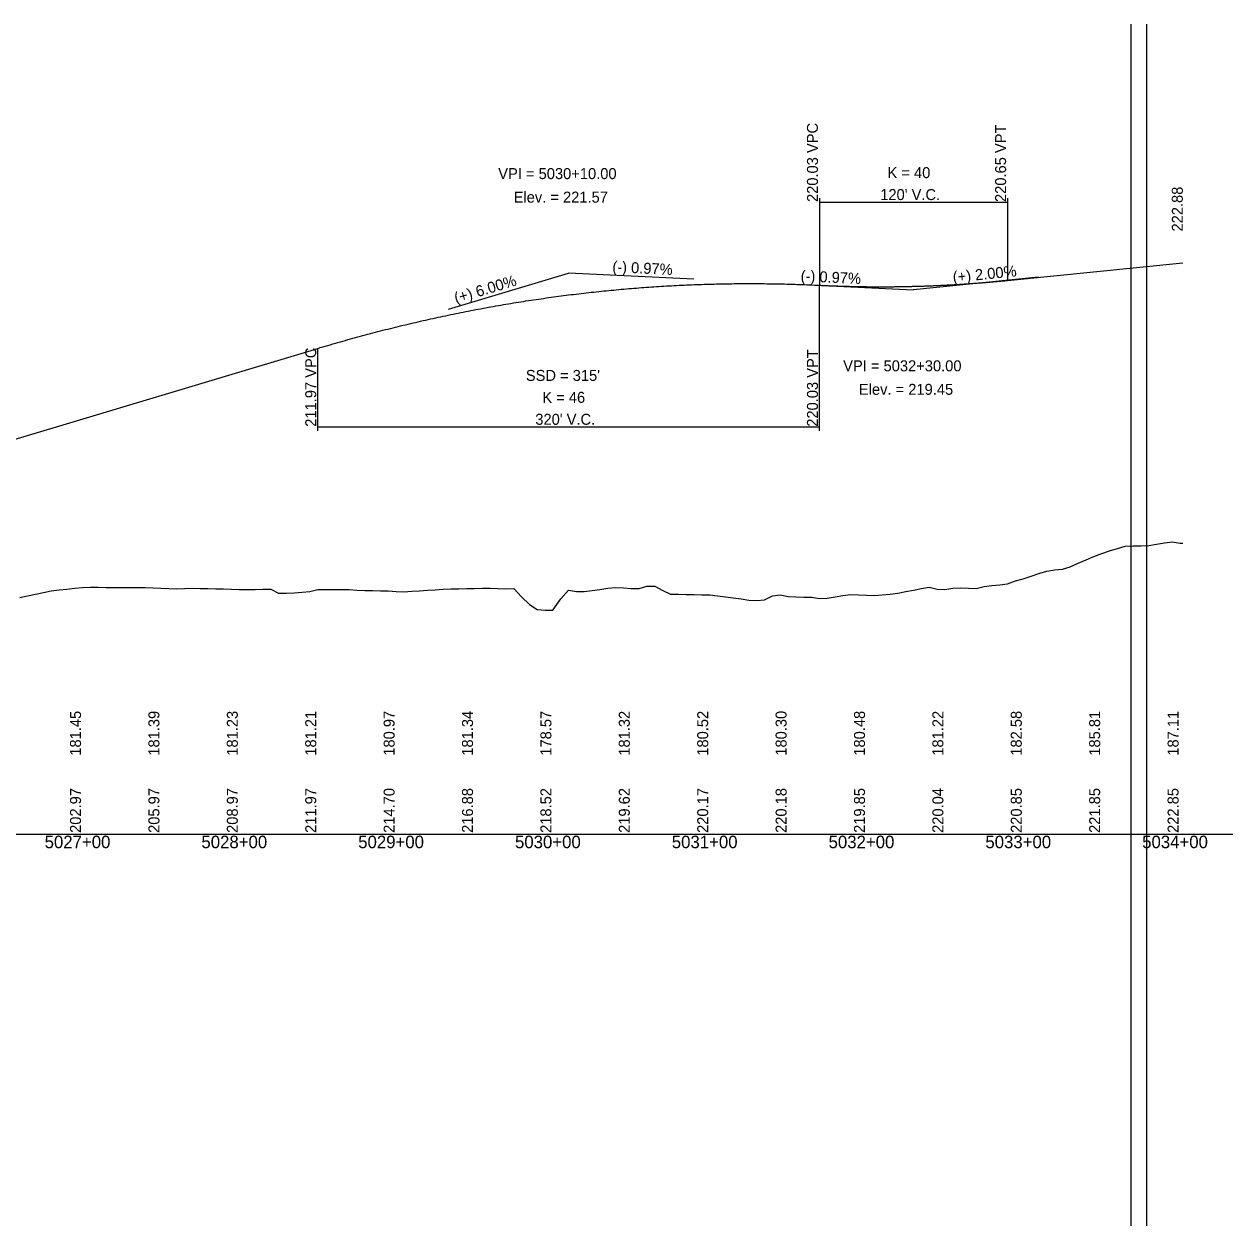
# Model space of a CAD drawing. Extents: x 1876258 to 1932803, y 754739 to 837911.
# Drawn here: x 1915332 to 1916098, y 787739 to 788506 of the extents above; entities that cross this region are included whole.
import ezdxf

# ---------------------------------------------------------------- set-up
doc = ezdxf.new("R2010")
doc.units = 0
for name, color, linetype in [('Default', 7, 'Continuous'), ('RD_DDB_GradeTX', 7, 'Continuous'), ('RD_DDB_Profile_EX', 7, 'Continuous'), ('RD_DDB_Profile_Lbl', 7, 'Continuous'), ('RD_DDB_Profile_PR', 7, 'Continuous'), ('RD_DDB_StaTX', 7, 'Continuous'), ('RD_DDB_StripGrade', 7, 'Continuous'), ('RD_DDB_VCLbl', 7, 'Continuous'), ('RD_GPK_Profile_Cell', 7, 'Continuous')]:
    doc.layers.add(name, color=color, linetype=linetype)

msp = doc.modelspace()

# ---------------------------------------------------------------- linework, layer by layer
at = {"layer": 'Default'}
for p, q in [((1916038.02, 787739.14), (1916038.02, 788505.91)), ((1916048.02, 787739.14), (1916048.02, 788505.91))]:
    msp.add_line(p, q, dxfattribs=at)
at = {"layer": 'RD_DDB_GradeTX'}
for p, q in [((1915602.66, 788324.01), (1915679.29, 788347)), ((1915759.2, 788343.14), (1915679.29, 788347)), ((1915819.38, 788340.23), (1915899.29, 788336.37)), ((1915978.89, 788344.33), (1915899.29, 788336.37))]:
    msp.add_line(p, q, dxfattribs=at)
at = {"layer": 'RD_DDB_Profile_EX'}
for points in [[(1915964.26, 788150.67), (1915969.26, 788152.05), (1915974.26, 788153.65), (1915979.26, 788155.28), (1915984.26, 788156.9), (1915989.26, 788157.82), (1915994.26, 788158.06), (1915999.26, 788159.6), (1916004.26, 788161.87), (1916009.26, 788164.15), (1916014.26, 788166.26), (1916019.26, 788168.19), (1916024.26, 788169.77), (1916029.26, 788171.31), (1916034.26, 788172.84), (1916039.26, 788172.97), (1916044.26, 788173.11), (1916049.26, 788173.25), (1916054.26, 788174.02), (1916059.26, 788175.01), (1916064.26, 788175.64), (1916069.26, 788174.7), (1916071.01, 788174.7)], [(1915964.26, 788150.67), (1915969.26, 788152.05), (1915974.26, 788153.65), (1915979.26, 788155.28), (1915984.26, 788156.9), (1915989.26, 788157.82), (1915994.26, 788158.06), (1915999.26, 788159.6), (1916004.26, 788161.87), (1916009.26, 788164.15), (1916014.26, 788166.26), (1916019.26, 788168.19), (1916024.26, 788169.77), (1916029.26, 788171.31), (1916034.26, 788172.84), (1916039.26, 788172.97), (1916044.26, 788173.11), (1916049.26, 788173.25), (1916054.26, 788174.02), (1916059.26, 788175.01), (1916064.26, 788175.64), (1916069.26, 788174.7), (1916071.01, 788174.7)], [(1915464.26, 788145.4), (1915469.26, 788145.27), (1915474.26, 788145.11), (1915479.26, 788145.23), (1915484.26, 788145.34), (1915489.26, 788145.46), (1915494.26, 788142.91), (1915499.26, 788142.81), (1915504.26, 788143.14), (1915509.26, 788143.48), (1915514.26, 788143.86), (1915519.26, 788145.22), (1915524.26, 788145.21), (1915529.26, 788145.22), (1915534.26, 788145.24), (1915539.26, 788145.16), (1915544.26, 788144.72), (1915549.26, 788144.6), (1915554.26, 788144.51), (1915559.26, 788144.42), (1915564.26, 788144.33), (1915569.26, 788143.98), (1915574.26, 788143.77), (1915579.26, 788144.09), (1915584.26, 788144.41), (1915589.26, 788144.74), (1915594.26, 788145.06), (1915599.26, 788145.38), (1915604.26, 788145.5), (1915609.26, 788145.62), (1915614.26, 788145.74), (1915619.26, 788145.85), (1915624.26, 788145.97), (1915629.26, 788146.07), (1915634.26, 788145.86), (1915639.26, 788145.65), (1915644.26, 788145.91), (1915649.26, 788140.45), (1915654.26, 788135.5), (1915659.26, 788132.36), (1915664.26, 788132.01), (1915669.26, 788131.93), (1915674.26, 788139.31), (1915679.26, 788144.73), (1915684.26, 788143.96), (1915689.26, 788143.87), (1915694.26, 788144.5), (1915699.26, 788145.27), (1915704.26, 788146.03), (1915709.26, 788146.52), (1915714.26, 788146.24), (1915719.26, 788145.75), (1915724.26, 788145.82), (1915729.26, 788147.31), (1915734.26, 788147.32), (1915739.26, 788144.61), (1915744.26, 788142.28), (1915749.26, 788142.15), (1915754.26, 788142.02), (1915759.26, 788141.88), (1915764.26, 788141.81), (1915769.26, 788141.77), (1915774.26, 788141.22), (1915779.26, 788140.52), (1915784.26, 788139.85), (1915789.26, 788139.17), (1915794.26, 788138.45), (1915799.26, 788138.08), (1915804.26, 788138.61), (1915809.26, 788141.18), (1915814.26, 788141.76), (1915819.26, 788140.63), (1915824.26, 788140.51), (1915829.26, 788140.39), (1915834.26, 788140.26), (1915839.26, 788139.41), (1915844.26, 788139.6), (1915849.26, 788140.43), (1915854.26, 788141.25), (1915859.26, 788142.03), (1915864.26, 788141.79), (1915869.26, 788141.55), (1915874.26, 788141.4), (1915879.26, 788141.73), (1915884.26, 788142.28), (1915889.26, 788142.89), (1915894.26, 788143.81), (1915899.26, 788144.75), (1915904.26, 788145.8), (1915909.26, 788146.69), (1915914.26, 788145.49), (1915919.26, 788145.24), (1915924.26, 788146.02), (1915929.26, 788146.24), (1915934.26, 788146.03), (1915939.26, 788145.71), (1915944.26, 788147.09), (1915949.26, 788147.66), (1915954.26, 788148.22), (1915959.26, 788148.88), (1915964.26, 788150.67)], [(1915464.26, 788145.4), (1915469.26, 788145.27), (1915474.26, 788145.11), (1915479.26, 788145.23), (1915484.26, 788145.34), (1915489.26, 788145.46), (1915494.26, 788142.91), (1915499.26, 788142.81), (1915504.26, 788143.14), (1915509.26, 788143.48), (1915514.26, 788143.86), (1915519.26, 788145.22), (1915524.26, 788145.21), (1915529.26, 788145.22), (1915534.26, 788145.24), (1915539.26, 788145.16), (1915544.26, 788144.72), (1915549.26, 788144.6), (1915554.26, 788144.51), (1915559.26, 788144.42), (1915564.26, 788144.33), (1915569.26, 788143.98), (1915574.26, 788143.77), (1915579.26, 788144.09), (1915584.26, 788144.41), (1915589.26, 788144.74), (1915594.26, 788145.06), (1915599.26, 788145.38), (1915604.26, 788145.5), (1915609.26, 788145.62), (1915614.26, 788145.74), (1915619.26, 788145.85), (1915624.26, 788145.97), (1915629.26, 788146.07), (1915634.26, 788145.86), (1915639.26, 788145.65), (1915644.26, 788145.91), (1915649.26, 788140.45), (1915654.26, 788135.5), (1915659.26, 788132.36), (1915664.26, 788132.01), (1915669.26, 788131.93), (1915674.26, 788139.31), (1915679.26, 788144.73), (1915684.26, 788143.96), (1915689.26, 788143.87), (1915694.26, 788144.5), (1915699.26, 788145.27), (1915704.26, 788146.03), (1915709.26, 788146.52), (1915714.26, 788146.24), (1915719.26, 788145.75), (1915724.26, 788145.82), (1915729.26, 788147.31), (1915734.26, 788147.32), (1915739.26, 788144.61), (1915744.26, 788142.28), (1915749.26, 788142.15), (1915754.26, 788142.02), (1915759.26, 788141.88), (1915764.26, 788141.81), (1915769.26, 788141.77), (1915774.26, 788141.22), (1915779.26, 788140.52), (1915784.26, 788139.85), (1915789.26, 788139.17), (1915794.26, 788138.45), (1915799.26, 788138.08), (1915804.26, 788138.61), (1915809.26, 788141.18), (1915814.26, 788141.76), (1915819.26, 788140.63), (1915824.26, 788140.51), (1915829.26, 788140.39), (1915834.26, 788140.26), (1915839.26, 788139.41), (1915844.26, 788139.6), (1915849.26, 788140.43), (1915854.26, 788141.25), (1915859.26, 788142.03), (1915864.26, 788141.79), (1915869.26, 788141.55), (1915874.26, 788141.4), (1915879.26, 788141.73), (1915884.26, 788142.28), (1915889.26, 788142.89), (1915894.26, 788143.81), (1915899.26, 788144.75), (1915904.26, 788145.8), (1915909.26, 788146.69), (1915914.26, 788145.49), (1915919.26, 788145.24), (1915924.26, 788146.02), (1915929.26, 788146.24), (1915934.26, 788146.03), (1915939.26, 788145.71), (1915944.26, 788147.09), (1915949.26, 788147.66), (1915954.26, 788148.22), (1915959.26, 788148.88), (1915964.26, 788150.67)], [(1915329.26, 788140.12), (1915334.26, 788141.16), (1915339.26, 788142.21), (1915344.26, 788143.25), (1915349.26, 788144.29), (1915354.26, 788144.97), (1915359.26, 788145.44), (1915364.26, 788145.92), (1915369.26, 788146.4), (1915374.26, 788146.61), (1915379.26, 788146.57), (1915384.26, 788146.54), (1915389.26, 788146.51), (1915394.26, 788146.48), (1915399.26, 788146.45), (1915404.26, 788146.42), (1915409.26, 788146.55), (1915414.26, 788146.32), (1915419.26, 788146.08), (1915424.26, 788145.85), (1915429.26, 788145.55), (1915434.26, 788145.85), (1915439.26, 788146.02), (1915444.26, 788145.89), (1915449.26, 788145.77), (1915454.26, 788145.65), (1915459.26, 788145.52), (1915464.26, 788145.4)], [(1915329.26, 788140.12), (1915334.26, 788141.16), (1915339.26, 788142.21), (1915344.26, 788143.25), (1915349.26, 788144.29), (1915354.26, 788144.97), (1915359.26, 788145.44), (1915364.26, 788145.92), (1915369.26, 788146.4), (1915374.26, 788146.61), (1915379.26, 788146.57), (1915384.26, 788146.54), (1915389.26, 788146.51), (1915394.26, 788146.48), (1915399.26, 788146.45), (1915404.26, 788146.42), (1915409.26, 788146.55), (1915414.26, 788146.32), (1915419.26, 788146.08), (1915424.26, 788145.85), (1915429.26, 788145.55), (1915434.26, 788145.85), (1915439.26, 788146.02), (1915444.26, 788145.89), (1915449.26, 788145.77), (1915454.26, 788145.65), (1915459.26, 788145.52), (1915464.26, 788145.4)]]:
    msp.add_lwpolyline(points, dxfattribs=at)
at = {"layer": 'RD_DDB_Profile_PR'}
for p, q in [((1915959.29, 788342.37), (1916071.01, 788353.54)), ((1915284.29, 788228.5), (1915519.29, 788299))]:
    msp.add_line(p, q, dxfattribs=at)
for points in [[(1915519.29, 788299), (1915525.69, 788300.9), (1915532.09, 788302.75), (1915538.49, 788304.56), (1915544.89, 788306.32), (1915551.29, 788308.04), (1915557.69, 788309.72), (1915564.09, 788311.35), (1915570.49, 788312.93), (1915576.89, 788314.47), (1915583.29, 788315.97), (1915589.69, 788317.42), (1915596.09, 788318.83), (1915602.49, 788320.19), (1915608.89, 788321.51), (1915615.29, 788322.78), (1915621.69, 788324.01), (1915628.09, 788325.2), (1915634.49, 788326.34), (1915640.89, 788327.43), (1915647.29, 788328.48), (1915653.69, 788329.49), (1915660.09, 788330.45), (1915666.49, 788331.37), (1915672.89, 788332.24), (1915679.29, 788333.07), (1915685.69, 788333.85), (1915692.09, 788334.59), (1915698.49, 788335.28), (1915704.89, 788335.93), (1915711.29, 788336.54), (1915717.69, 788337.1), (1915724.09, 788337.61), (1915730.49, 788338.08), (1915736.89, 788338.51), (1915743.29, 788338.89), (1915749.69, 788339.23), (1915756.09, 788339.52), (1915762.49, 788339.77), (1915768.89, 788339.97), (1915775.29, 788340.13), (1915781.69, 788340.25), (1915788.09, 788340.32), (1915794.49, 788340.34), (1915800.89, 788340.32), (1915807.29, 788340.26), (1915813.69, 788340.15), (1915820.09, 788340), (1915826.49, 788339.8), (1915832.89, 788339.56), (1915839.29, 788339.27)], [(1915839.29, 788339.27), (1915841.69, 788339.16), (1915844.09, 788339.05), (1915846.49, 788338.95), (1915848.89, 788338.86), (1915851.29, 788338.78), (1915853.69, 788338.7), (1915856.09, 788338.63), (1915858.49, 788338.57), (1915860.89, 788338.51), (1915863.29, 788338.47), (1915865.69, 788338.43), (1915868.09, 788338.39), (1915870.49, 788338.36), (1915872.89, 788338.34), (1915875.29, 788338.33), (1915877.69, 788338.33), (1915880.09, 788338.33), (1915882.49, 788338.34), (1915884.89, 788338.35), (1915887.29, 788338.37), (1915889.69, 788338.4), (1915892.09, 788338.44), (1915894.49, 788338.49), (1915896.89, 788338.54), (1915899.29, 788338.6), (1915901.69, 788338.66), (1915904.09, 788338.73), (1915906.49, 788338.81), (1915908.89, 788338.9), (1915911.29, 788339), (1915913.69, 788339.1), (1915916.09, 788339.2), (1915918.49, 788339.32), (1915920.89, 788339.44), (1915923.29, 788339.57), (1915925.69, 788339.71), (1915928.09, 788339.85), (1915930.49, 788340), (1915932.89, 788340.16), (1915935.29, 788340.33), (1915937.69, 788340.5), (1915940.09, 788340.68), (1915942.49, 788340.87), (1915944.89, 788341.06), (1915947.29, 788341.26), (1915949.69, 788341.47), (1915952.09, 788341.68), (1915954.49, 788341.91), (1915956.89, 788342.13), (1915959.29, 788342.37)]]:
    msp.add_spline(points, degree=3, dxfattribs=at)
at = {"layer": 'RD_DDB_VCLbl'}
for p, q in [((1915839.29, 788394.87), (1915839.29, 788339.27)), ((1915839.29, 788392.37), (1915959.29, 788392.37)), ((1915959.29, 788394.87), (1915959.29, 788342.37)), ((1915839.29, 788246.5), (1915839.29, 788339.27)), ((1915519.29, 788246.5), (1915519.29, 788299)), ((1915519.29, 788249), (1915839.29, 788249))]:
    msp.add_line(p, q, dxfattribs=at)
at = {"layer": 'RD_GPK_Profile_Cell'}
msp.add_line((1914544, 787989.14), (1916244, 787989.14), dxfattribs=at)

# ---------------------------------------------------------------- texts
at = {"layer": 'RD_DDB_GradeTX'}
for s, rotation, p in [('(-) 0.97%', 357.23394, (1915707.03, 788347.66)), ('(-) 0.97%', 357.23394, (1915827.15, 788341.86)), ('(+) 2.00%', 5.71056, (1915924.63, 788340.92)), ('(+) 6.00%', 16.69924, (1915607.52, 788327.56))]:
    msp.add_text(s, height=7, rotation=rotation, dxfattribs=at).set_placement(p)
at = {"layer": 'RD_DDB_Profile_Lbl'}
for s, p in [('VPI = 5030+10.00', (1915634.39, 788407)), ('Elev. = 221.57', (1915644.23, 788392)), ('VPI = 5032+30.00', (1915854.39, 788284.37)), ('Elev. = 219.45', (1915864.43, 788269.37))]:
    msp.add_text(s, height=7, dxfattribs=at).set_placement(p)
msp.add_text('222.88', height=7, rotation=90, dxfattribs=at).set_placement((1916071.01, 788373.54))
at = {"layer": 'RD_DDB_StaTX'}
for s, p in [('5027+00', (1915345.08, 787980.14)), ('5028+00', (1915445.08, 787980.14)), ('5029+00', (1915545.08, 787980.14)), ('5030+00', (1915645.08, 787980.14)), ('5031+00', (1915745.08, 787980.14)), ('5032+00', (1915845.08, 787980.14)), ('5033+00', (1915945.08, 787980.14)), ('5034+00', (1916045.08, 787980.14))]:
    msp.add_text(s, height=8, dxfattribs=at).set_placement(p)
at = {"layer": 'RD_DDB_StripGrade'}
for s, p in [('220.03 VPC', (1915838.29, 788392.37)), ('220.65 VPT', (1915958.29, 788392.37)), ('211.97 VPC', (1915518.29, 788249)), ('220.03 VPT', (1915838.29, 788249)), ('181.45', (1915368.29, 788039.14)), ('181.39', (1915418.29, 788039.14)), ('181.23', (1915468.29, 788039.14)), ('181.21', (1915518.29, 788039.14)), ('180.97', (1915568.29, 788039.14)), ('181.34', (1915618.29, 788039.14)), ('178.57', (1915668.29, 788039.14)), ('181.32', (1915718.29, 788039.14)), ('180.52', (1915768.29, 788039.14)), ('180.30', (1915818.29, 788039.14)), ('180.48', (1915868.29, 788039.14)), ('181.22', (1915918.29, 788039.14)), ('182.58', (1915968.29, 788039.14)), ('185.81', (1916018.29, 788039.14)), ('187.11', (1916068.29, 788039.14)), ('202.97', (1915368.29, 787989.89)), ('205.97', (1915418.29, 787989.89)), ('208.97', (1915468.29, 787989.89)), ('211.97', (1915518.29, 787989.89)), ('214.70', (1915568.29, 787989.89)), ('216.88', (1915618.29, 787989.89)), ('218.52', (1915668.29, 787989.89)), ('219.62', (1915718.29, 787989.89)), ('220.17', (1915768.29, 787989.89)), ('220.18', (1915818.29, 787989.89)), ('219.85', (1915868.29, 787989.89)), ('220.04', (1915918.29, 787989.89)), ('220.85', (1915968.29, 787989.89)), ('221.85', (1916018.29, 787989.89)), ('222.85', (1916068.29, 787989.89))]:
    msp.add_text(s, height=7, rotation=90, dxfattribs=at).set_placement(p)
at = {"layer": 'RD_DDB_VCLbl'}
for s, p in [('K = 40', (1915882.67, 788407.62)), ("120' V.C.", (1915878.03, 788393.62)), ("SSD = 315'", (1915651.98, 788278.25)), ('K = 46', (1915662.51, 788264.25)), ("320' V.C.", (1915658.03, 788250.25))]:
    msp.add_text(s, height=7, dxfattribs=at).set_placement(p)

doc.saveas('drawing.dxf')
